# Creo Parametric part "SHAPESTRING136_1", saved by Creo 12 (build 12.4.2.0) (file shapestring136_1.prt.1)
Units: Custom; MM, KILOGRAM, SECS

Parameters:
  PTC_WM_ITERATION = "0"
  PTC_WM_VERSION = "-.0"
  PTC_WM_LIFECYCLE_STATE = "In Work"
  PTC_WM_LIFECYCLE = "MO_CADDocument"
  PTC_WM_CREATED_BY = "Maximilian Roepper (Z0017RMS: MO)"
  PTC_WM_CREATED_ON = "18-Sep-26 11:36:42 AM"
  PTC_WM_MODIFIED_BY = "Maximilian Roepper (Z0017RMS: MO)"
  PTC_WM_MODIFIED_ON = "18-Sep-26 11:36:46 AM"
  PDMLINKNUMBER = "PDM000071454999"
  PTC_WM_NAME = "shapestring136_1.prt"
  PTC_WM_NUMBER = "PDM000071454999"

Other parameters: WEIGHT, WEIGHT_FACTOR, WEIGHT_ADD, _MASS_TEMP, _DIFF_TEMP, MC_ERRORS, SUPPLIER

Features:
  1. coordinate system
  2. datum plane "PRT_YZ"
  3. datum plane "PRT_XY"
  4. datum plane "PRT_XZ"
  5. coordinate system
  6. datum axis
  7. datum axis
  8. datum axis
  9. coordinate system
  10. imported feature
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
Other named items: PRT, SIEMENS_MO, DRW_VIEW_ORG, PRT_X, PRT_Y, PRT_Z, CS0, ROUGH_GROB

Layers: 00_STD_CSYS-KSYS, 01_STD_PLANES-EBENEN, 02_STD_AXES-ACHSEN, 03_STD_CSYS-KSYS, 24_IMPORT_FEAT-IMPORT_KE, INTFCLR

Surfaces: 1 plane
